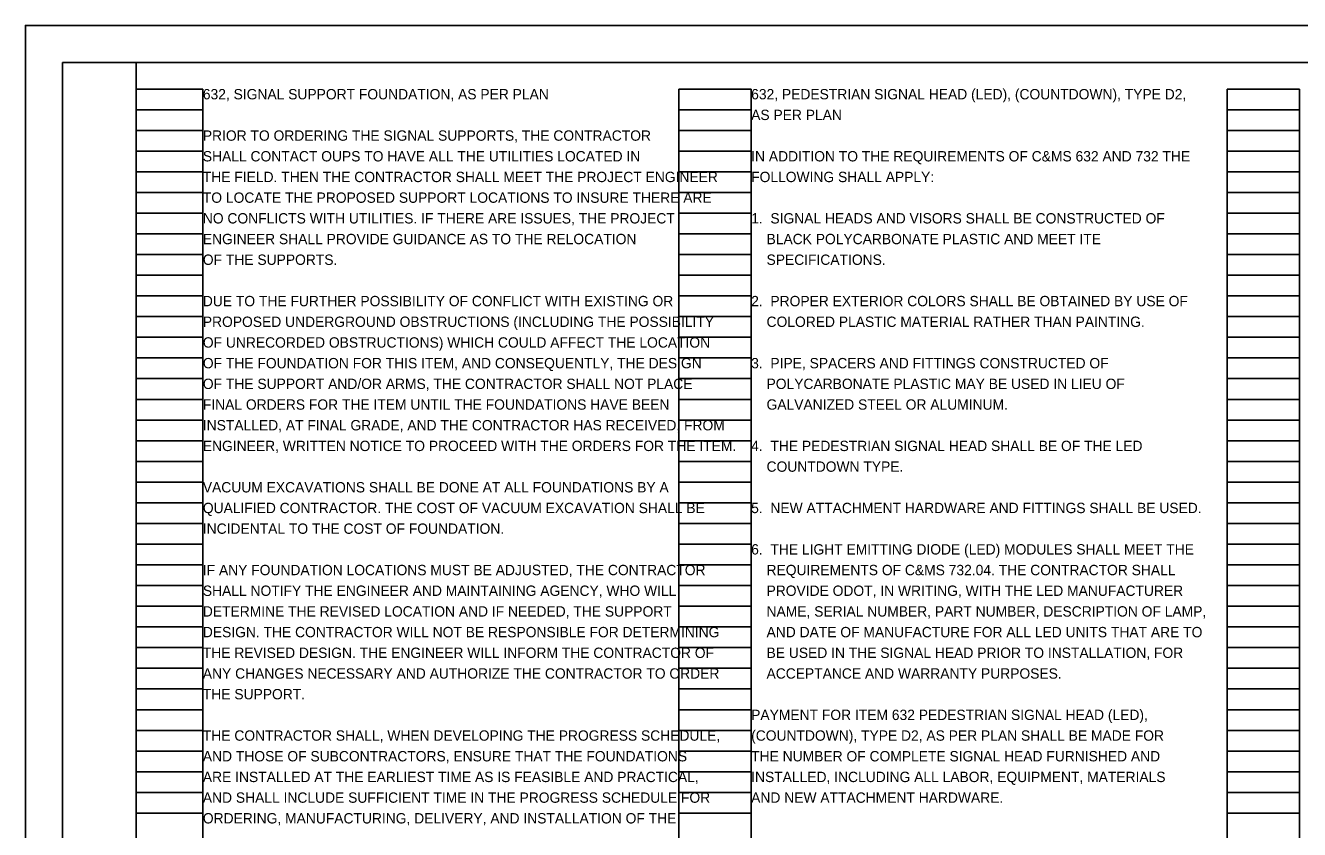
# Model space of a CAD drawing. Extents: x 0 to 34, y 0 to 36.2.
# Drawn here: x 0 to 17.24, y 11.12 to 22 of the extents above; entities that cross this region are included whole.
import ezdxf

# ---------------------------------------------------------------- set-up
doc = ezdxf.new("R2010")
doc.units = 0
for name, color, linetype in [('SH_Border', 7, 'Continuous'), ('SH_Cut_Line', 7, 'Continuous'), ('SH_Data', 7, 'Continuous'), ('SH_Text', 7, 'Continuous')]:
    doc.layers.add(name, color=color, linetype=linetype)

msp = doc.modelspace()

# ---------------------------------------------------------------- linework, layer by layer
at = {"layer": 'SH_Border'}
for points in [[(0.5, 21.5), (1.5, 21.5), (1.5, 0.5), (0.5, 0.5)], [(1.5, 21.5), (33.5, 21.5), (33.5, 0.5), (1.5, 0.5)]]:
    msp.add_lwpolyline(points, close=True, dxfattribs=at)
at = {"layer": 'SH_Cut_Line'}
msp.add_lwpolyline([(0, 0), (34, 0), (34, 22), (0, 22)], close=True, dxfattribs=at)
at = {"layer": 'SH_Data'}
for p, q in [((1.5, 0.98), (1.5, 21.14)), ((1.5, 21.14), (2.4, 21.14)), ((2.4, 0.98), (2.4, 21.14)), ((8.84, 0.98), (8.84, 21.14)), ((8.84, 21.14), (9.82, 21.14)), ((9.82, 0.98), (9.82, 21.14)), ((16.26, 0.98), (16.26, 21.14)), ((16.26, 21.14), (17.24, 21.14)), ((17.24, 0.98), (17.24, 21.14)), ((1.5, 20.86), (2.4, 20.86)), ((8.84, 20.86), (9.82, 20.86)), ((16.26, 20.86), (17.24, 20.86)), ((1.5, 20.58), (2.4, 20.58)), ((8.84, 20.58), (9.82, 20.58)), ((16.26, 20.58), (17.24, 20.58)), ((1.5, 20.3), (2.4, 20.3)), ((8.84, 20.3), (9.82, 20.3)), ((16.26, 20.3), (17.24, 20.3)), ((1.5, 20.02), (2.4, 20.02)), ((8.84, 20.02), (9.82, 20.02)), ((16.26, 20.02), (17.24, 20.02)), ((1.5, 19.74), (2.4, 19.74)), ((8.84, 19.74), (9.82, 19.74)), ((16.26, 19.74), (17.24, 19.74)), ((1.5, 19.46), (2.4, 19.46)), ((8.84, 19.46), (9.82, 19.46)), ((16.26, 19.46), (17.24, 19.46)), ((1.5, 19.18), (2.4, 19.18)), ((8.84, 19.18), (9.82, 19.18)), ((16.26, 19.18), (17.24, 19.18)), ((1.5, 18.9), (2.4, 18.9)), ((8.84, 18.9), (9.82, 18.9)), ((16.26, 18.9), (17.24, 18.9)), ((1.5, 18.62), (2.4, 18.62)), ((8.84, 18.62), (9.82, 18.62)), ((16.26, 18.62), (17.24, 18.62)), ((1.5, 18.34), (2.4, 18.34)), ((8.84, 18.34), (9.82, 18.34)), ((16.26, 18.34), (17.24, 18.34)), ((1.5, 18.06), (2.4, 18.06)), ((8.84, 18.06), (9.82, 18.06)), ((16.26, 18.06), (17.24, 18.06)), ((1.5, 17.78), (2.4, 17.78)), ((8.84, 17.78), (9.82, 17.78)), ((16.26, 17.78), (17.24, 17.78)), ((1.5, 17.5), (2.4, 17.5)), ((8.84, 17.5), (9.82, 17.5)), ((16.26, 17.5), (17.24, 17.5)), ((1.5, 17.22), (2.4, 17.22)), ((8.84, 17.22), (9.82, 17.22)), ((16.26, 17.22), (17.24, 17.22)), ((1.5, 16.94), (2.4, 16.94)), ((8.84, 16.94), (9.82, 16.94)), ((16.26, 16.94), (17.24, 16.94)), ((1.5, 16.66), (2.4, 16.66)), ((8.84, 16.66), (9.82, 16.66)), ((16.26, 16.66), (17.24, 16.66)), ((1.5, 16.38), (2.4, 16.38)), ((8.84, 16.38), (9.82, 16.38)), ((16.26, 16.38), (17.24, 16.38)), ((1.5, 16.1), (2.4, 16.1)), ((8.84, 16.1), (9.82, 16.1)), ((16.26, 16.1), (17.24, 16.1)), ((1.5, 15.82), (2.4, 15.82)), ((8.84, 15.82), (9.82, 15.82)), ((16.26, 15.82), (17.24, 15.82)), ((1.5, 15.54), (2.4, 15.54)), ((8.84, 15.54), (9.82, 15.54)), ((16.26, 15.54), (17.24, 15.54)), ((1.5, 15.26), (2.4, 15.26)), ((8.84, 15.26), (9.82, 15.26)), ((16.26, 15.26), (17.24, 15.26)), ((1.5, 14.98), (2.4, 14.98)), ((8.84, 14.98), (9.82, 14.98)), ((16.26, 14.98), (17.24, 14.98)), ((1.5, 14.7), (2.4, 14.7)), ((8.84, 14.7), (9.82, 14.7)), ((16.26, 14.7), (17.24, 14.7)), ((1.5, 14.42), (2.4, 14.42)), ((8.84, 14.42), (9.82, 14.42)), ((16.26, 14.42), (17.24, 14.42)), ((1.5, 14.14), (2.4, 14.14)), ((8.84, 14.14), (9.82, 14.14)), ((16.26, 14.14), (17.24, 14.14)), ((1.5, 13.86), (2.4, 13.86)), ((8.84, 13.86), (9.82, 13.86)), ((16.26, 13.86), (17.24, 13.86)), ((1.5, 13.58), (2.4, 13.58)), ((8.84, 13.58), (9.82, 13.58)), ((16.26, 13.58), (17.24, 13.58)), ((1.5, 13.3), (2.4, 13.3)), ((8.84, 13.3), (9.82, 13.3)), ((16.26, 13.3), (17.24, 13.3)), ((1.5, 13.02), (2.4, 13.02)), ((8.84, 13.02), (9.82, 13.02)), ((16.26, 13.02), (17.24, 13.02)), ((1.5, 12.74), (2.4, 12.74)), ((8.84, 12.74), (9.82, 12.74)), ((16.26, 12.74), (17.24, 12.74)), ((1.5, 12.46), (2.4, 12.46)), ((8.84, 12.46), (9.82, 12.46)), ((16.26, 12.46), (17.24, 12.46)), ((1.5, 12.18), (2.4, 12.18)), ((8.84, 12.18), (9.82, 12.18)), ((16.26, 12.18), (17.24, 12.18)), ((1.5, 11.9), (2.4, 11.9)), ((8.84, 11.9), (9.82, 11.9)), ((16.26, 11.9), (17.24, 11.9)), ((1.5, 11.62), (2.4, 11.62)), ((8.84, 11.62), (9.82, 11.62)), ((16.26, 11.62), (17.24, 11.62)), ((1.5, 11.34), (2.4, 11.34)), ((8.84, 11.34), (9.82, 11.34)), ((16.26, 11.34), (17.24, 11.34))]:
    msp.add_line(p, q, dxfattribs=at)

# ---------------------------------------------------------------- texts
at = {"layer": 'SH_Text'}
for s, p in [('632, SIGNAL SUPPORT FOUNDATION, AS PER PLAN', (2.4, 21)), ('632, PEDESTRIAN SIGNAL HEAD (LED), (COUNTDOWN), TYPE D2,', (9.82, 21)), ('AS PER PLAN', (9.82, 20.72)), ('PRIOR TO ORDERING THE SIGNAL SUPPORTS, THE CONTRACTOR', (2.4, 20.44)), ('SHALL CONTACT OUPS TO HAVE ALL THE UTILITIES LOCATED IN', (2.4, 20.16)), ('IN ADDITION TO THE REQUIREMENTS OF C&MS 632 AND 732 THE', (9.82, 20.16)), ('THE FIELD. THEN THE CONTRACTOR SHALL MEET THE PROJECT ENGINEER ', (2.4, 19.88)), ('FOLLOWING SHALL APPLY:', (9.82, 19.88)), ('TO LOCATE THE PROPOSED SUPPORT LOCATIONS TO INSURE THERE ARE ', (2.4, 19.6)), ('NO CONFLICTS WITH UTILITIES. IF THERE ARE ISSUES, THE PROJECT', (2.4, 19.32)), ('1.  SIGNAL HEADS AND VISORS SHALL BE CONSTRUCTED OF', (9.82, 19.32)), ('ENGINEER SHALL PROVIDE GUIDANCE AS TO THE RELOCATION', (2.4, 19.04)), ('    BLACK POLYCARBONATE PLASTIC AND MEET ITE', (9.82, 19.04)), ('OF THE SUPPORTS.', (2.4, 18.76)), ('    SPECIFICATIONS.', (9.82, 18.76)), ('DUE TO THE FURTHER POSSIBILITY OF CONFLICT WITH EXISTING OR ', (2.4, 18.2)), ('2.  PROPER EXTERIOR COLORS SHALL BE OBTAINED BY USE OF', (9.82, 18.2)), ('PROPOSED UNDERGROUND OBSTRUCTIONS (INCLUDING THE POSSIBILITY ', (2.4, 17.92)), ('    COLORED PLASTIC MATERIAL RATHER THAN PAINTING.', (9.82, 17.92)), ('OF UNRECORDED OBSTRUCTIONS) WHICH COULD AFFECT THE LOCATION ', (2.4, 17.64)), ('OF THE FOUNDATION FOR THIS ITEM, AND CONSEQUENTLY, THE DESIGN ', (2.4, 17.36)), ('3.  PIPE, SPACERS AND FITTINGS CONSTRUCTED OF', (9.82, 17.36)), ('OF THE SUPPORT AND/OR ARMS, THE CONTRACTOR SHALL NOT PLACE ', (2.4, 17.08)), ('    POLYCARBONATE PLASTIC MAY BE USED IN LIEU OF', (9.82, 17.08)), ('FINAL ORDERS FOR THE ITEM UNTIL THE FOUNDATIONS HAVE BEEN ', (2.4, 16.8)), ('    GALVANIZED STEEL OR ALUMINUM.', (9.82, 16.8)), ('INSTALLED, AT FINAL GRADE, AND THE CONTRACTOR HAS RECEIVED, FROM', (2.4, 16.52)), ('ENGINEER, WRITTEN NOTICE TO PROCEED WITH THE ORDERS FOR THE ITEM.', (2.4, 16.24)), ('4.  THE PEDESTRIAN SIGNAL HEAD SHALL BE OF THE LED', (9.82, 16.24)), ('    COUNTDOWN TYPE.', (9.82, 15.96)), ('VACUUM EXCAVATIONS SHALL BE DONE AT ALL FOUNDATIONS BY A', (2.4, 15.68)), ('QUALIFIED CONTRACTOR. THE COST OF VACUUM EXCAVATION SHALL BE ', (2.4, 15.4)), ('5.  NEW ATTACHMENT HARDWARE AND FITTINGS SHALL BE USED.', (9.82, 15.4)), ('INCIDENTAL TO THE COST OF FOUNDATION.', (2.4, 15.12)), ('6.  THE LIGHT EMITTING DIODE (LED) MODULES SHALL MEET THE', (9.82, 14.84)), ('IF ANY FOUNDATION LOCATIONS MUST BE ADJUSTED, THE CONTRACTOR ', (2.4, 14.56)), ('    REQUIREMENTS OF C&MS 732.04. THE CONTRACTOR SHALL', (9.82, 14.56)), ('SHALL NOTIFY THE ENGINEER AND MAINTAINING AGENCY, WHO WILL ', (2.4, 14.28)), ('    PROVIDE ODOT, IN WRITING, WITH THE LED MANUFACTURER', (9.82, 14.28)), ('DETERMINE THE REVISED LOCATION AND IF NEEDED, THE SUPPORT ', (2.4, 14)), ('    NAME, SERIAL NUMBER, PART NUMBER, DESCRIPTION OF LAMP,', (9.82, 14)), ('DESIGN. THE CONTRACTOR WILL NOT BE RESPONSIBLE FOR DETERMINING ', (2.4, 13.72)), ('    AND DATE OF MANUFACTURE FOR ALL LED UNITS THAT ARE TO', (9.82, 13.72)), ('THE REVISED DESIGN. THE ENGINEER WILL INFORM THE CONTRACTOR OF ', (2.4, 13.44)), ('    BE USED IN THE SIGNAL HEAD PRIOR TO INSTALLATION, FOR', (9.82, 13.44)), ('ANY CHANGES NECESSARY AND AUTHORIZE THE CONTRACTOR TO ORDER', (2.4, 13.16)), ('    ACCEPTANCE AND WARRANTY PURPOSES.', (9.82, 13.16)), ('THE SUPPORT.', (2.4, 12.88)), ('PAYMENT FOR ITEM 632 PEDESTRIAN SIGNAL HEAD (LED),', (9.82, 12.6)), ('THE CONTRACTOR SHALL, WHEN DEVELOPING THE PROGRESS SCHEDULE,', (2.4, 12.32)), ('(COUNTDOWN), TYPE D2, AS PER PLAN SHALL BE MADE FOR', (9.82, 12.32)), ('AND THOSE OF SUBCONTRACTORS, ENSURE THAT THE FOUNDATIONS', (2.4, 12.04)), ('THE NUMBER OF COMPLETE SIGNAL HEAD FURNISHED AND', (9.82, 12.04)), ('ARE INSTALLED AT THE EARLIEST TIME AS IS FEASIBLE AND PRACTICAL, ', (2.4, 11.76)), ('INSTALLED, INCLUDING ALL LABOR, EQUIPMENT, MATERIALS', (9.82, 11.76)), ('AND SHALL INCLUDE SUFFICIENT TIME IN THE PROGRESS SCHEDULE FOR ', (2.4, 11.48)), ('AND NEW ATTACHMENT HARDWARE.', (9.82, 11.48)), ('ORDERING, MANUFACTURING, DELIVERY, AND INSTALLATION OF THE ', (2.4, 11.2))]:
    msp.add_text(s, height=0.14, dxfattribs=at).set_placement(p)

doc.saveas('drawing.dxf')
